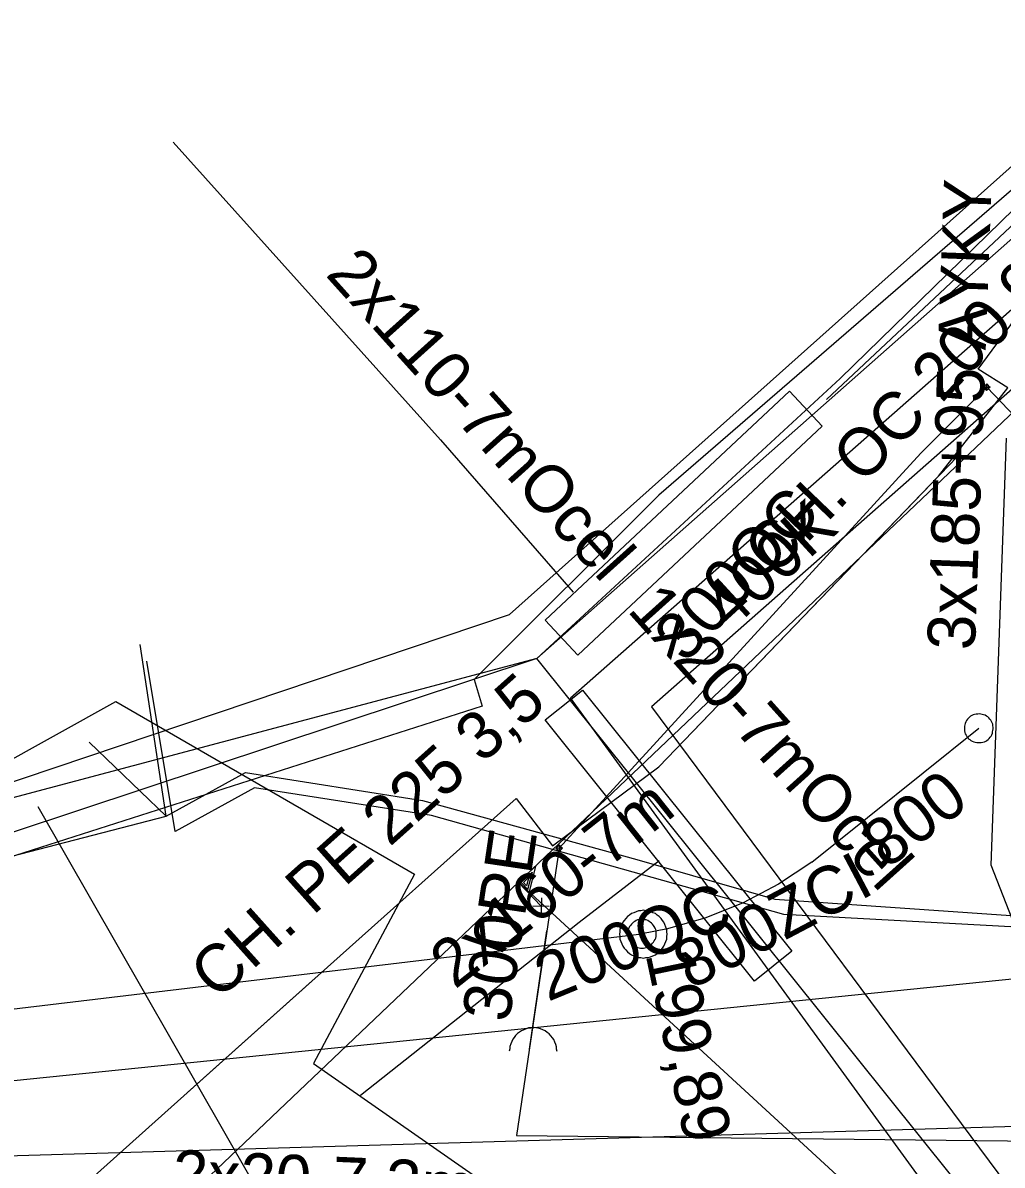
# Model space of a CAD drawing. Extents: x -746464 to -745690, y -1051581 to -1049993.
# Drawn here: x -746338.99 to -746318.51, y -1051024.28 to -1051000.39 of the extents above; entities that cross this region are included whole.
import ezdxf

# ---------------------------------------------------------------- set-up
doc = ezdxf.new("R2010")
doc.units = 0
for name, color, linetype in [('04_CETIN_NN', 7, 'Continuous'), ('04_CETIN_sdelovaci_podzem', 7, 'Continuous'), ('37_TVNET_sdelovaci_aktualizace_2019', 7, 'Continuous'), ('45_Eltodo_sdelovaci_kabel_ovladaci', 7, 'Continuous'), ('45_Eltodo_vedeni_NN_zemni', 7, 'Continuous'), ('48_Prazs_plynarenska_STL', 7, 'Continuous'), ('48_Prazs_plynarenska_STL_chranicka', 7, 'Continuous'), ('48_Prazs_plynarenska_STL_popisy', 7, 'Continuous'), ('51_PVaK_kanal_destova_overena poloha', 7, 'Continuous'), ('51_PVaK_kanal_jednotna_neoverena poloha_pripojka', 7, 'Continuous'), ('51_PVaK_kanal_jednotna_overena poloha_rad', 7, 'Continuous'), ('51_PVaK_kanal_objekty', 7, 'Continuous'), ('51_PVaK_kanal_popisy', 7, 'Continuous'), ('51_PVaK_vodovod_chranicky_objekty', 7, 'Continuous'), ('51_PVaK_vodovod_overena poloha_rad', 7, 'Continuous'), ('51_PVaK_vodovod_popisy', 7, 'Continuous'), ('51_PVaK_vodovod_zruseno_overena poloha', 7, 'Continuous'), ('55_PREdi_chranicky', 7, 'Continuous'), ('55_PREdi_NN', 7, 'Continuous'), ('55_PREdi_NN_popisy', 7, 'Continuous'), ('55_PREdi_stavby_popisy', 7, 'Continuous'), ('55_PREdi_ZRUSENE_elektro', 7, 'Continuous')]:
    doc.layers.add(name, color=color, linetype=linetype)

msp = doc.modelspace()

# ---------------------------------------------------------------- linework, layer by layer
at = {"layer": '04_CETIN_NN'}
for points in [[(-746335.99, -1051016.98), (-746334.33, -1051016.07), (-746330.63, -1051016.65), (-746326.15, -1051017.89), (-746323.26, -1051018.72), (-746316.11, -1051019.21), (-746311.04, -1051016.89), (-746310.77, -1051016.09), (-746309.83, -1051011.33), (-746309.52, -1051005.24)], [(-746341.51, -1051018.41), (-746335.99, -1051016.98)]]:
    msp.add_lwpolyline(points, dxfattribs=at)
at = {"layer": '04_CETIN_sdelovaci_podzem'}
for points in [[(-746266.32, -1050920.34), (-746265.41, -1050926.73), (-746265.01, -1050940.81), (-746268.22, -1050968.45), (-746268.96, -1050971.47), (-746269.85, -1050973.88), (-746270.1, -1050973.71), (-746273.43, -1050971.5), (-746273.76, -1050971.27), (-746284.05, -1050978.88), (-746291.4, -1050985.15), (-746294.75, -1050988.08), (-746309.55, -1050996.3), (-746325.69, -1051010.27), (-746329.55, -1051014.12), (-746329.38, -1051014.68), (-746351.52, -1051021.76)], [(-746335.99, -1051016.98), (-746334.33, -1051016.07), (-746330.63, -1051016.65), (-746326.15, -1051017.89), (-746323.26, -1051018.72), (-746316.11, -1051019.21), (-746311.04, -1051016.89), (-746310.77, -1051016.09), (-746309.83, -1051011.33), (-746309.52, -1051005.24)], [(-746335.99, -1051016.98), (-746336.53, -1051013.39)], [(-746335.99, -1051016.98), (-746337.6, -1051015.43)], [(-746330.63, -1051016.65), (-746326.15, -1051017.89)], [(-746341.51, -1051018.41), (-746335.99, -1051016.98)]]:
    msp.add_lwpolyline(points, dxfattribs=at)
at = {"layer": '37_TVNET_sdelovaci_aktualizace_2019'}
msp.add_lwpolyline([(-746309.52, -1051005.24), (-746310.96, -1051016.855), (-746316.022, -1051019.419), (-746323.07, -1051019.04), (-746330.44, -1051016.97), (-746334.14, -1051016.39), (-746335.8, -1051017.3), (-746336.391, -1051013.738)], dxfattribs=at)
at = {"layer": '45_Eltodo_sdelovaci_kabel_ovladaci'}
msp.add_lwpolyline([(-746458.107, -1051040.596), (-746452.238, -1051038.914), (-746452.533, -1051024.817), (-746441.647, -1051021.908), (-746427.884, -1051017.81), (-746425.007, -1051017.632), (-746423.494, -1051014.247), (-746406.379, -1051019.532), (-746393.969, -1051021.364), (-746377.076, -1051023.037), (-746371.357, -1051023.39), (-746350.592, -1051020.748), (-746343.378, -1051018.106), (-746337.043, -1051014.584), (-746330.796, -1051018.194), (-746332.907, -1051022.157), (-746327.98, -1051025.591), (-746302.693, -1051026.653), (-746280.345, -1051027.533), (-746279.938, -1051027.788)], dxfattribs=at)
at = {"layer": '45_Eltodo_vedeni_NN_zemni'}
msp.add_lwpolyline([(-746308.467, -1050994.546), (-746313.26, -1050999.889), (-746322.179, -1051008.269)], dxfattribs=at)
at = {"layer": '48_Prazs_plynarenska_STL'}
msp.add_lwpolyline([(-746343.01, -1051029.87), (-746342.98, -1051029.42), (-746332.94, -1051020.43), (-746328.67, -1051016.61), (-746327.91, -1051017.6), (-746325.69, -1051015.95), (-746319.84, -1051009.87), (-746318.39, -1051008.02), (-746319.01, -1051007.63), (-746317.08, -1051005.01), (-746313.738, -1051002.152), (-746308.46, -1050997.64), (-746302.4, -1050994.1), (-746287, -1050984.1), (-746276.62, -1050976.16), (-746273.63, -1050976.714)], dxfattribs=at)
at = {"layer": '48_Prazs_plynarenska_STL_chranicka'}
for points in [[(-746325.688, -1051015.948), (-746319.448, -1051009.462)], [(-746332.938, -1051020.428), (-746335.545, -1051022.762)]]:
    msp.add_lwpolyline(points, dxfattribs=at)
at = {"layer": '51_PVaK_kanal_destova_overena poloha'}
for p, q in [((-746322.49, -1051017.94), (-746318.997, -1051015.143)), ((-746366.29, -1051024.26), (-746326.04, -1051019.44))]:
    msp.add_line(p, q, dxfattribs=at)
msp.add_lwpolyline([(-746322.49, -1051017.94), (-746323.185, -1051018.406), (-746323.926, -1051018.797), (-746324.703, -1051019.109), (-746325.509, -1051019.338), (-746326.04, -1051019.44)], dxfattribs=at)
at = {"layer": '51_PVaK_kanal_jednotna_neoverena poloha_pripojka'}
msp.add_line((-746308.49, -1051036.89), (-746328.62, -1051018.364), dxfattribs=at)
at = {"layer": '51_PVaK_kanal_jednotna_overena poloha_rad'}
msp.add_lwpolyline([(-746337.51, -1051026.82), (-746328.62, -1051018.364), (-746307.39, -1050998.17)], dxfattribs=at)
at = {"layer": '51_PVaK_kanal_objekty'}
for p, q in [((-746328.142, -1051018.687), (-746328.15, -1051019.028)), ((-746327.977, -1051018.87), (-746328.321, -1051018.862))]:
    msp.add_line(p, q, dxfattribs=at)
for points in [[(-746318.765, -1051014.949), (-746318.784, -1051014.925), (-746318.808, -1051014.906), (-746318.832, -1051014.887), (-746318.861, -1051014.871), (-746318.895, -1051014.86), (-746318.924, -1051014.853), (-746318.954, -1051014.846), (-746318.988, -1051014.843), (-746319.018, -1051014.845), (-746319.048, -1051014.847), (-746319.083, -1051014.852), (-746319.114, -1051014.862), (-746319.141, -1051014.877), (-746319.168, -1051014.892), (-746319.191, -1051014.911), (-746319.214, -1051014.931), (-746319.234, -1051014.955), (-746319.253, -1051014.979), (-746319.268, -1051015.008), (-746319.28, -1051015.041), (-746319.287, -1051015.071), (-746319.294, -1051015.1), (-746319.297, -1051015.134), (-746319.295, -1051015.164), (-746319.293, -1051015.195), (-746319.288, -1051015.229), (-746319.278, -1051015.26), (-746319.263, -1051015.287), (-746319.248, -1051015.315), (-746319.229, -1051015.338), (-746319.209, -1051015.361), (-746319.185, -1051015.38), (-746319.161, -1051015.4), (-746319.132, -1051015.415), (-746319.099, -1051015.426), (-746319.069, -1051015.433), (-746319.04, -1051015.44), (-746319.006, -1051015.443), (-746318.976, -1051015.442), (-746318.945, -1051015.44), (-746318.91, -1051015.434), (-746318.879, -1051015.424), (-746318.852, -1051015.409), (-746318.825, -1051015.395), (-746318.802, -1051015.375), (-746318.779, -1051015.356), (-746318.76, -1051015.332), (-746318.74, -1051015.307), (-746318.725, -1051015.279), (-746318.713, -1051015.245), (-746318.707, -1051015.216), (-746318.7, -1051015.186), (-746318.697, -1051015.152), (-746318.698, -1051015.122), (-746318.7, -1051015.092), (-746318.706, -1051015.057), (-746318.716, -1051015.026), (-746318.731, -1051014.999), (-746318.745, -1051014.972), (-746318.765, -1051014.949)], [(-746328.145, -1051018.865), (-746328.62, -1051018.366), (-746328.264, -1051018.028), (-746328.406, -1051018.591)], [(-746328.427, -1051018.516), (-746328.565, -1051018.371), (-746328.338, -1051018.155), (-746328.43, -1051018.519)], [(-746328.451, -1051018.439), (-746328.52, -1051018.366), (-746328.403, -1051018.255), (-746328.453, -1051018.441)], [(-746325.51, -1051019.45), (-746325.52, -1051019.4), (-746325.52, -1051019.35), (-746325.54, -1051019.3), (-746325.56, -1051019.25), (-746325.58, -1051019.2), (-746325.61, -1051019.16), (-746325.64, -1051019.12), (-746325.68, -1051019.08), (-746325.72, -1051019.05), (-746325.76, -1051019.02), (-746325.81, -1051019), (-746325.86, -1051018.98), (-746325.91, -1051018.96), (-746325.96, -1051018.96), (-746326.01, -1051018.95), (-746326.06, -1051018.96), (-746326.11, -1051018.96), (-746326.16, -1051018.98), (-746326.21, -1051019), (-746326.26, -1051019.02), (-746326.3, -1051019.05), (-746326.34, -1051019.08), (-746326.38, -1051019.12), (-746326.41, -1051019.16), (-746326.44, -1051019.2), (-746326.46, -1051019.25), (-746326.48, -1051019.3), (-746326.5, -1051019.35), (-746326.5, -1051019.4), (-746326.51, -1051019.45), (-746326.5, -1051019.5), (-746326.5, -1051019.55), (-746326.48, -1051019.6), (-746326.46, -1051019.65), (-746326.44, -1051019.7), (-746326.41, -1051019.74), (-746326.38, -1051019.78), (-746326.34, -1051019.82), (-746326.3, -1051019.85), (-746326.26, -1051019.88), (-746326.21, -1051019.9), (-746326.16, -1051019.92), (-746326.11, -1051019.94), (-746326.06, -1051019.94), (-746326.01, -1051019.95), (-746325.96, -1051019.94), (-746325.91, -1051019.94), (-746325.86, -1051019.92), (-746325.81, -1051019.9), (-746325.76, -1051019.88), (-746325.72, -1051019.85), (-746325.68, -1051019.82), (-746325.64, -1051019.78), (-746325.61, -1051019.74), (-746325.58, -1051019.7), (-746325.56, -1051019.65), (-746325.54, -1051019.6), (-746325.52, -1051019.55), (-746325.52, -1051019.5), (-746325.51, -1051019.45)], [(-746325.74, -1051019.44), (-746325.74, -1051019.41), (-746325.746, -1051019.38), (-746325.752, -1051019.35), (-746325.764, -1051019.32), (-746325.782, -1051019.29), (-746325.8, -1051019.266), (-746325.818, -1051019.242), (-746325.842, -1051019.218), (-746325.866, -1051019.2), (-746325.89, -1051019.182), (-746325.92, -1051019.164), (-746325.95, -1051019.152), (-746325.98, -1051019.146), (-746326.01, -1051019.14), (-746326.04, -1051019.14), (-746326.07, -1051019.14), (-746326.1, -1051019.146), (-746326.13, -1051019.152), (-746326.16, -1051019.164), (-746326.19, -1051019.182), (-746326.214, -1051019.2), (-746326.238, -1051019.218), (-746326.262, -1051019.242), (-746326.28, -1051019.266), (-746326.298, -1051019.29), (-746326.316, -1051019.32), (-746326.328, -1051019.35), (-746326.334, -1051019.38), (-746326.34, -1051019.41), (-746326.34, -1051019.44), (-746326.34, -1051019.47), (-746326.334, -1051019.5), (-746326.328, -1051019.53), (-746326.316, -1051019.56), (-746326.298, -1051019.59), (-746326.28, -1051019.614), (-746326.262, -1051019.638), (-746326.238, -1051019.662), (-746326.214, -1051019.68), (-746326.19, -1051019.698), (-746326.16, -1051019.716), (-746326.13, -1051019.728), (-746326.1, -1051019.734), (-746326.07, -1051019.74), (-746326.04, -1051019.74), (-746326.01, -1051019.74), (-746325.98, -1051019.734), (-746325.95, -1051019.728), (-746325.92, -1051019.716), (-746325.89, -1051019.698), (-746325.866, -1051019.68), (-746325.842, -1051019.662), (-746325.818, -1051019.638), (-746325.8, -1051019.614), (-746325.782, -1051019.59), (-746325.764, -1051019.56), (-746325.752, -1051019.53), (-746325.746, -1051019.5), (-746325.74, -1051019.47), (-746325.74, -1051019.44)]]:
    msp.add_lwpolyline(points, dxfattribs=at)
at = {"layer": '51_PVaK_vodovod_chranicky_objekty'}
for p, q in [((-746318.902, -1051008.009), (-746318.888, -1051007.995)), ((-746318.761, -1051008.011), (-746318.902, -1051008.009)), ((-746318.902, -1051008.009), (-746318.888, -1051008.023)), ((-746318.833, -1051008.081), (-746318.847, -1051008.066)), ((-746318.83, -1051007.939), (-746318.844, -1051007.953)), ((-746318.833, -1051008.081), (-746318.83, -1051007.939)), ((-746318.833, -1051008.081), (-746318.818, -1051008.067)), ((-746318.83, -1051007.939), (-746318.816, -1051007.954)), ((-746318.761, -1051008.011), (-746318.775, -1051007.997)), ((-746318.761, -1051008.011), (-746318.775, -1051008.025)), ((-746327.841, -1051017.655), (-746327.827, -1051017.64)), ((-746327.699, -1051017.648), (-746327.841, -1051017.655)), ((-746327.841, -1051017.655), (-746327.826, -1051017.668)), ((-746327.773, -1051017.581), (-746327.787, -1051017.596)), ((-746327.773, -1051017.581), (-746327.767, -1051017.722)), ((-746327.773, -1051017.581), (-746327.758, -1051017.594)), ((-746327.699, -1051017.648), (-746327.714, -1051017.635)), ((-746327.699, -1051017.648), (-746327.713, -1051017.663)), ((-746327.767, -1051017.722), (-746327.782, -1051017.709)), ((-746327.767, -1051017.722), (-746327.753, -1051017.707)), ((-746328.392, -1051021.852), (-746328.026, -1051019.379))]:
    msp.add_line(p, q, dxfattribs=at)
for points in [[(-746318.866, -1051007.974), (-746318.87, -1051007.977), (-746318.873, -1051007.982), (-746318.875, -1051007.986), (-746318.878, -1051007.991), (-746318.879, -1051007.996), (-746318.88, -1051008.001), (-746318.881, -1051008.006), (-746318.881, -1051008.012), (-746318.88, -1051008.017), (-746318.88, -1051008.022), (-746318.878, -1051008.027), (-746318.876, -1051008.032), (-746318.874, -1051008.037), (-746318.871, -1051008.041), (-746318.867, -1051008.045), (-746318.864, -1051008.048), (-746318.86, -1051008.051), (-746318.856, -1051008.054), (-746318.851, -1051008.056), (-746318.845, -1051008.058), (-746318.84, -1051008.059), (-746318.835, -1051008.059), (-746318.83, -1051008.06), (-746318.825, -1051008.059), (-746318.82, -1051008.058), (-746318.814, -1051008.057), (-746318.809, -1051008.055), (-746318.805, -1051008.052), (-746318.8, -1051008.05), (-746318.797, -1051008.046), (-746318.793, -1051008.043), (-746318.79, -1051008.038), (-746318.787, -1051008.034), (-746318.785, -1051008.029), (-746318.784, -1051008.024), (-746318.783, -1051008.019), (-746318.782, -1051008.014), (-746318.782, -1051008.008), (-746318.782, -1051008.003), (-746318.783, -1051007.998), (-746318.784, -1051007.993), (-746318.786, -1051007.988), (-746318.789, -1051007.983), (-746318.792, -1051007.979), (-746318.795, -1051007.975), (-746318.799, -1051007.972), (-746318.803, -1051007.969), (-746318.807, -1051007.966), (-746318.812, -1051007.964), (-746318.818, -1051007.962), (-746318.823, -1051007.961), (-746318.828, -1051007.961), (-746318.833, -1051007.96), (-746318.838, -1051007.961), (-746318.843, -1051007.962), (-746318.849, -1051007.963), (-746318.854, -1051007.965), (-746318.858, -1051007.968), (-746318.862, -1051007.97), (-746318.866, -1051007.974)], [(-746327.804, -1051017.688), (-746327.8, -1051017.692), (-746327.796, -1051017.694), (-746327.791, -1051017.697), (-746327.786, -1051017.699), (-746327.781, -1051017.7), (-746327.776, -1051017.7), (-746327.771, -1051017.701), (-746327.765, -1051017.701), (-746327.76, -1051017.7), (-746327.755, -1051017.699), (-746327.75, -1051017.697), (-746327.745, -1051017.695), (-746327.741, -1051017.692), (-746327.736, -1051017.689), (-746327.733, -1051017.685), (-746327.73, -1051017.681), (-746327.727, -1051017.677), (-746327.724, -1051017.673), (-746327.723, -1051017.668), (-746327.721, -1051017.662), (-746327.721, -1051017.657), (-746327.72, -1051017.652), (-746327.721, -1051017.646), (-746327.722, -1051017.641), (-746327.722, -1051017.637), (-746327.724, -1051017.631), (-746327.726, -1051017.626), (-746327.729, -1051017.622), (-746327.732, -1051017.618), (-746327.736, -1051017.615), (-746327.74, -1051017.611), (-746327.744, -1051017.609), (-746327.749, -1051017.606), (-746327.754, -1051017.604), (-746327.759, -1051017.603), (-746327.764, -1051017.602), (-746327.769, -1051017.602), (-746327.775, -1051017.602), (-746327.78, -1051017.603), (-746327.785, -1051017.604), (-746327.79, -1051017.606), (-746327.795, -1051017.608), (-746327.799, -1051017.611), (-746327.803, -1051017.614), (-746327.807, -1051017.618), (-746327.81, -1051017.621), (-746327.813, -1051017.626), (-746327.815, -1051017.63), (-746327.817, -1051017.635), (-746327.819, -1051017.641), (-746327.819, -1051017.646), (-746327.82, -1051017.651), (-746327.819, -1051017.656), (-746327.818, -1051017.661), (-746327.817, -1051017.666), (-746327.816, -1051017.672), (-746327.813, -1051017.677), (-746327.81, -1051017.681), (-746327.807, -1051017.685), (-746327.804, -1051017.688)], [(-746327.816, -1051021.906), (-746327.825, -1051021.856), (-746327.825, -1051021.806), (-746327.844, -1051021.756), (-746327.864, -1051021.706), (-746327.883, -1051021.655), (-746327.913, -1051021.615), (-746327.942, -1051021.575), (-746327.982, -1051021.534), (-746328.021, -1051021.504), (-746328.061, -1051021.474), (-746328.111, -1051021.453), (-746328.161, -1051021.432), (-746328.211, -1051021.412), (-746328.261, -1051021.411), (-746328.31, -1051021.401), (-746328.361, -1051021.41), (-746328.411, -1051021.41), (-746328.461, -1051021.429), (-746328.511, -1051021.449), (-746328.561, -1051021.468), (-746328.601, -1051021.498), (-746328.642, -1051021.527), (-746328.682, -1051021.567), (-746328.713, -1051021.607), (-746328.743, -1051021.646), (-746328.764, -1051021.696), (-746328.784, -1051021.746), (-746328.805, -1051021.796), (-746328.805, -1051021.846), (-746328.816, -1051021.896)]]:
    msp.add_lwpolyline(points, dxfattribs=at)
at = {"layer": '51_PVaK_vodovod_overena poloha_rad'}
for points in [[(-746298.34, -1050992.36), (-746299.36, -1050992.94), (-746307.39, -1050999.94), (-746315.48, -1051007.82), (-746317.16, -1051009.75), (-746318.83, -1051008.01), (-746320.21, -1051009.39), (-746327.77, -1051017.65), (-746328.66, -1051023.66), (-746316.47, -1051023.79), (-746316.22, -1051021.61), (-746314.389, -1051021.739)], [(-746388.07, -1051038.69), (-746387.45, -1051038.37), (-746387.14, -1051038.19), (-746383.68, -1051036.98), (-746364.73, -1051037.15), (-746364.02, -1051025.04), (-746317.41, -1051020.29), (-746317.31, -1051019.61), (-746316.75, -1051015.31)]]:
    msp.add_lwpolyline(points, dxfattribs=at)
at = {"layer": '51_PVaK_vodovod_zruseno_overena poloha'}
msp.add_lwpolyline([(-746316.404, -1051018.82), (-746316.79, -1051023.43), (-746364.5, -1051024.83), (-746365.72, -1051037.75), (-746388.47, -1051038.77)], dxfattribs=at)
at = {"layer": '55_PREdi_chranicky'}
for points in [[(-746327.379, -1051013.613), (-746328.063, -1051012.884), (-746322.958, -1051008.095), (-746322.274, -1051008.824), (-746327.379, -1051013.613)], [(-746328.067, -1051014.969), (-746327.286, -1051014.344), (-746322.909, -1051019.806), (-746323.69, -1051020.431), (-746328.067, -1051014.969)]]:
    msp.add_lwpolyline(points, close=True, dxfattribs=at)
at = {"layer": '55_PREdi_NN'}
for points in [[(-746317.039, -1051026.572), (-746318.823, -1051026.486), (-746327.536, -1051014.504), (-746311.76, -1051000.614), (-746293.31, -1050989.459), (-746270.27, -1050970.787), (-746268.96, -1050925.936), (-746274.791, -1050900.587), (-746280.96, -1050896.444), (-746281.902, -1050889.994), (-746278.512, -1050882.884), (-746280.08, -1050871.671), (-746281.012, -1050871.801)], [(-746282.685, -1050891.909), (-746281.949, -1050896.915), (-746275.592, -1050901.576), (-746269.964, -1050926.03), (-746271.259, -1050970.363), (-746293.852, -1050988.609), (-746312.231, -1050999.532), (-746328.24, -1051013.684), (-746340.582, -1051017.778)], [(-746268.166, -1050933.051), (-746269.281, -1050971.258), (-746292.768, -1050990.309), (-746311.619, -1051002.168), (-746325.841, -1051014.693), (-746317.835, -1051025.475), (-746316.924, -1051025.527)], [(-746341.029, -1051016.873), (-746328.808, -1051012.762), (-746313.362, -1050998.967), (-746302.643, -1050992.619), (-746303.484, -1050987.178), (-746303.591, -1050987.126), (-746303.48, -1050985.223)], [(-746328.24, -1051013.684), (-746321.898, -1051007.825), (-746313.207, -1050999.349), (-746302.062, -1050992.631)], [(-746328.24, -1051013.684), (-746340.853, -1051017.038), (-746342.979, -1051017.603), (-746351.074, -1051020.516), (-746363.112, -1051022.249), (-746367.995, -1051022.985), (-746373.78, -1051023.267), (-746393.79, -1051021.091), (-746394.655, -1051020.827)], [(-746298.351, -1051026.8), (-746317.519, -1051026.231), (-746318.234, -1051026.166), (-746328.24, -1051013.684)]]:
    msp.add_lwpolyline(points, dxfattribs=at)
at = {"layer": '55_PREdi_NN_popisy'}
msp.add_lwpolyline([(-746315.802, -1051025.51), (-746318.74, -1051018.003), (-746318.417, -1051009.073)], dxfattribs=at)
at = {"layer": '55_PREdi_stavby_popisy'}
for points in [[(-746335.846, -1051002.881), (-746330.25, -1051009.109), (-746327.481, -1051012.296)], [(-746331.926, -1051022.819), (-746327.355, -1051019.196), (-746325.677, -1051017.91)]]:
    msp.add_lwpolyline(points, dxfattribs=at)
at = {"layer": '55_PREdi_ZRUSENE_elektro'}
msp.add_lwpolyline([(-746338.669, -1051016.78), (-746333.659, -1051025.534), (-746319.053, -1051026.098)], dxfattribs=at)

# ---------------------------------------------------------------- texts
at = {"layer": '48_Prazs_plynarenska_STL_popisy'}
for s, rotation, p in [('CH. OC 200 9', 46.1074, (-746323.273, -1051011.995)), ('CH. PE 225 3,5', 41.8375, (-746334.915, -1051020.856))]:
    msp.add_text(s, height=1, rotation=rotation, dxfattribs=at).set_placement(p)
at = {"layer": '51_PVaK_kanal_popisy'}
for s, rotation, p in [('400K', 42.5658, (-746324.198, -1051013.129)), ('800 ', 37.6849, (-746320.922, -1051018.107)), ('800ZCI', 27.7783, (-746325.026, -1051020.622)), ('199,89', 281.8566, (-746325.967, -1051019.868))]:
    msp.add_text(s, height=1, rotation=rotation, dxfattribs=at).set_placement(p)
at = {"layer": '51_PVaK_vodovod_popisy'}
for s, rotation, p in [('300OC', 47.532, (-746325.127, -1051013.804)), ('300PE', 81.5796, (-746328.818, -1051021.311)), ('200OC', 22.3933, (-746328.008, -1051020.867))]:
    msp.add_text(s, height=1, rotation=rotation, dxfattribs=at).set_placement(p)
at = {"layer": '55_PREdi_NN_popisy'}
msp.add_text('3x185+95 AYKY', height=1, rotation=87.9319, dxfattribs=at).set_placement((-746319.079, -1051013.52))
at = {"layer": '55_PREdi_stavby_popisy'}
for s, rotation, p in [('2x110-7mOcel  1x20-7mOcel', 311.9394, (-746332.676, -1051005.661)), ('2x160-7m', 38.3986, (-746329.951, -1051020.615)), ('2x20-7.3m', 357.5051, (-746335.875, -1051024.954))]:
    msp.add_text(s, height=1, rotation=rotation, dxfattribs=at).set_placement(p)

doc.saveas('drawing.dxf')
